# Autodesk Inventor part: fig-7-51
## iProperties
Shininess: 77.0
Length Units: 11269
Angle Units: 11279
Time Units: 11290
Mass Units: 11283
Length Display Precision: 3
Angle Display Precision: 2
Created: 2002-01
Part Number: fig-7-51
Document SubType Name: Modeling
Designer: ***
Density: 1 g/cm^3
Density: 0.0
Volumn: 0.0
Area: 0.0
PropertySet Name: Model Information
Control State: 0
Master: False
Checked Out: False
Author: ***
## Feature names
1. Extrusion2
2. FaceDraft8
